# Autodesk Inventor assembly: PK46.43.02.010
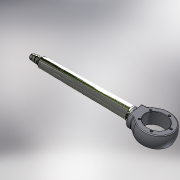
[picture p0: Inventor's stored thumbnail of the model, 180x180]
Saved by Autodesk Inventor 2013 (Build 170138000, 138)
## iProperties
Shininess: 64.0
Length Units: 11269
Angle Units: 11279
Time Units: 11290
Mass Units: 11283
Length Display Precision: 3
Angle Display Precision: 2
Compacted: True
Created: 2004-11
Part Number: PK46.43.02.010
Document SubType Name: Assembly
Designer: ELarisa
Manufacturer: Standard
Standards Organization: Custom
Density: 0.0
Volumn: 0.0
Area: 0.0
PropertySet Name: Model Information
Control State: 0
Master: False
Checked Out: False
Checked Out Date: 2008-10-09
Last Check In Date: 2008-10-09
Author: ELarisa
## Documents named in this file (3)
- C:\Product Design Suite 2013 Test Drive\Dynamic Simulation\Workspace\Assy, Chassis, Front\PK46.43.02.010.iam
- C:\Product Design Suite 2013 Test Drive\Dynamic Simulation\Workspace\Assy, Chassis, Front\PK46.43.02.001.ipt
- C:\Product Design Suite 2013 Test Drive\Dynamic Simulation\Workspace\Assy, Chassis, Front\PK46.43.02.008.ipt
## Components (2 placed, 2 different names)
1. PK46.43.02.001:1 — Вставка:1
2. PK46.43.02.008:1
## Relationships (1: Insert 1)
- Вставка:1 [Insert]: PK46.43.02.001:1
